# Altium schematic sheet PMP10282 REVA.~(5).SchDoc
size 431 x 279 mm; Date: Not shown in title block; ApprovedBy: Not shown in title block; CheckedBy: Not shown in title block; Author: Not shown in title block; CompanyName: Not shown in title block; Engineer: Not shown in title block; Organization: Not shown in title block; Address1: Not shown in title block; Address2: Not shown in title block; Address3: Not shown in title block; Address4: Not shown in title block; DocumentNumber: 1; Revision: Use project parameter SCH_Rev; SheetNumber: 1; SheetTotal: 1; PageSetup: Record=PageOptions|CenterHorizontal=True|CenterVertical=True|PrintScale=1.00|XCorrection=1.00|YCorrection=1.00|PrintKind=0|BorderSize=5000000|LeftOffset=0|BottomOffset=0|Orientation=2|PaperLength=1000|PaperWidth=1000|Scale=100|PaperSource=15|PrintQuality=600|MediaType=1|DitherType=10|PaperKind=Letter|PrintScaleMode=1
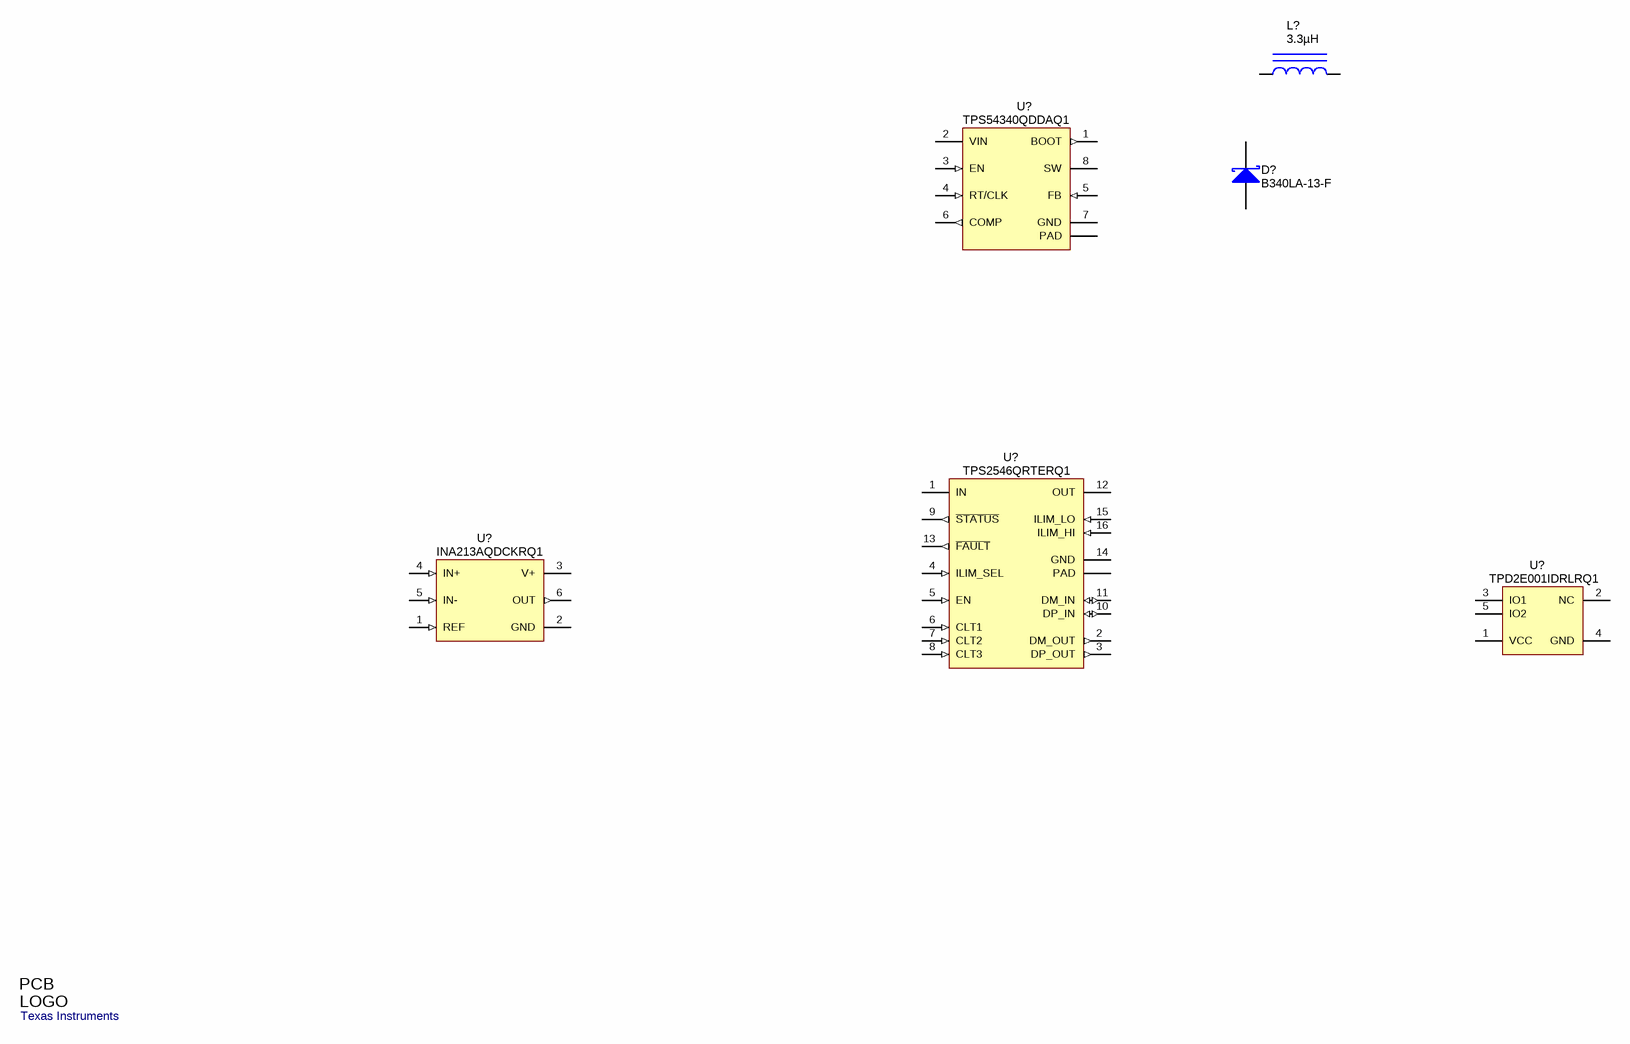
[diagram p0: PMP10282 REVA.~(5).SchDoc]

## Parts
(Parts that share a designator on the sheet are numbered #1, #2 ... from top to bottom, then left to right.)
D?  B340LA-13-F  [SMA]
L?  ValueDisplayed: 3.3µH  [SPM6530]  (hidden comment: SPM6530T-3R3M)
Logo1  Texas Instruments  [TI_Stacked_Overlay_Small]  (no BOM)
U?#1  TPS54340QDDAQ1  [DDA0008E_N]
U?#2  TPS2546QRTERQ1  [RTE0016C]
U?#3  TPD2E001IDRLRQ1  [DRL0005A]
U?#4  INA213AQDCKRQ1  [DCK0006A_N]

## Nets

Not connected (* = marked no-connect by the designer): D? 1(K) 2(A); L? 1 2; U?#1 1(BOOT) 2(VIN) 3(EN) 4(RT/CLK) 5(FB) 6(COMP) 7(GND) 8(SW) 9(PAD); U?#2 1(IN) 2(DM_OUT) 3(DP_OUT) 4(ILIM_SEL) 5(EN) 6(CLT1) 7(CLT2) 8(CLT3) 9(~{STATUS}) 10(DP_IN) 11(DM_IN) 12(OUT) 13(~{FAULT}) 14(GND) 15(ILIM_LO) 16(ILIM_HI) 17(PAD); U?#3 1(VCC) 2(NC) 3(IO1) 4(GND) 5(IO2); U?#4 1(REF) 2(GND) 3(V+) 4(IN+) 5(IN-) 6(OUT)

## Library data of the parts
D? = B340LA-13-F: Diode, Schottky, 40V, 3A, SMA; Manufacturer: Diodes Inc.; U/M: EA; Vf_V: 0.45; Value2: 0.45V; Io_A: 3; Vr_V: 40; TJmax_C: 125; RJC_CperW: 25
L? = SPM6530T-3R3M: Inductor, Shielded, Ferrite, 3.3uH, 6.8A, 0.0297 ohm, SMD; Manufacturer: TDK; Ind_H: 3.3E-6; Imax_A: 6.8; Irms: 6.8A @ 40C rise; Isat: 7.3A @ 20% inductance drop; DCR_ohm: 0.0297
Logo1 = TI_Logo: Texas Instrument Corporate Signature; SymbolCreator: a0412235
U?#1 = TPS54340DDA: 42 V Input, 3.5 A, Step Down DC-DC Converter with Eco-mode, DDA0008E; Alternate Manufacturer: None; Manufacturer: Texas Instruments; SymbolCreator: a0411947; CompType: IC; U/M: EA
U?#2 = TPS2546RTE: USB Charging Port Controller and Power Switch with Load Detection, RTE0016C; Alternate Manufacturer: None; Manufacturer: Texas Instruments; SymbolCreator: a0411947; CompType: IC; U/M: EA
U?#3 = TPD2E001IDRLRQ1: Automotive Catalog Low-Capacitance + / - 15 kV ESD-Protection Array for High-Speed Data Inter, 2 Channels, -40 to +85 degC, 5-pin SOT (DRL), Green (RoHS & no Sb/Br); Manufacturer: Texas Instruments; Alternate Manufacturer: None; Alternate PartNumber: Equivalent; Breakdown Voltage(Min)(V): 11; IEC 61000-4-2 Air-Gap(+/- kV): 15; IEC 61000-4-2 Contact(+/- kV): 8; IO Capacitance(Typ)(pF): 1.5; IO Leakage Current(nA): 1; SubFamily: ESD Solution; USB High Speed: TRUE
U?#4 = INA213AIDCK: Voltage Output, High or Low Side Measurement, Bi-Directional Zero-Drift Series Current-Shunt Monitor, DCK0006A; Alternate Manufacturer: None; Manufacturer: Texas Instruments; SymbolCreator: a0411947; CompType: IC; U/M: EA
